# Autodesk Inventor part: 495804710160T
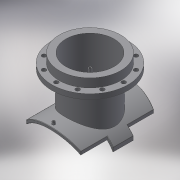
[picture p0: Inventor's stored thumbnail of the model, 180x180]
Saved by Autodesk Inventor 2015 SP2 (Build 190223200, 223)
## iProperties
Created: 2017-10
Part Number: 495804710160T
Material: Generic
Description: PLASSON FLANGED BRANCH SADDLE 560-630X250
Document SubType Name: Modeling
Designer: KIM
Density: 1 g/cm^3
Appearance: Default
Author: KIM
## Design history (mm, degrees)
derived "495904.ipt"
feature "Solid1::495904.ipt"
feature "Solid2::495904.ipt"
tag "TaggingFeature1"
body "Solid1"
other parameters: "d1" = 15, "d4" = 0, "d6" = 105, "d7" = 0, "d11" = 3.15, "d12" = 340.6, "d13" = 14, "d14" = 189, "d16" = 5 deg, "d18" = 4, "d19" = 14, "d20" = 0, "d21" = 3, "d22" = 0, "d23" = 555, "d36" = 189, "d38" = 0, "d39" = 2, "d40" = 225, "d43" = 395, "d46" = 256, "d47" = 16, "d48" = 10.4, "d49" = 157.5, "d51" = 642.6, "d53" = 0, "d54" = 22, "d55" = 175, "d57" = 0, "d59" = 360 deg, "d61" = 26, "d63" = 0, "H_" = 225, "x_" = 15, "D_" = 16, "D_1" = 395, "t_" = 26, "s_" = 22
